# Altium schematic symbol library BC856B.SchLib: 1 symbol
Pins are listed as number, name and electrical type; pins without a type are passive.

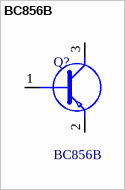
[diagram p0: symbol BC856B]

## BC856B
designator Q?
Bipolar Transistors - BJT BJT, SOT-23, 65V, 100mA, PNP; Manufacturer_Name: Diotec; Geometry.Height: 1.1mm
footprint SOT95P230X110-3N
pins: 1 B, 2 E, 3 C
